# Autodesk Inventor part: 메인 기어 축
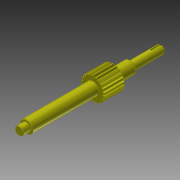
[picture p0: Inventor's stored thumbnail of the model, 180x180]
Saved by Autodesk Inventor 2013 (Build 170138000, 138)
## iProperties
Created: 2018-12
Part Number: 메인 기어 축
Material: 강철, 연강
Document SubType Name: Modeling
Designer: mduedu
Categories: <?xml version="1.0" encoding="UTF-16"?> <MemberInstance><Categories><FamilyTemplate><FamilyTemplateParameter ValueType="xs:double" Id="1" ObjectReferenceKey="da
Density: 7.86 g/cm^3
Mass: 139.66 g
Surface Area: 68.5733 cm^2
Volume: 17.7684 cm^3
CustomPartVersion: 1
Author: mduedu
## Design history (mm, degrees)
sketch "Sketch1"
  geometry: C1 r 11.3 at (0, 0)
  constraints: 1 centre point
  dimensions: "d0" = 22.6 diameter of C1 (= da_da)
extrude "Extrusion1" new body sketch "Sketch1" distance "d1" = 20 (= da_b); taper "d2" = 0 deg
workplane "Work Plane2"
sketch "Sketch2"
  geometry: C1 r 11.3 at (0, 0) reference; C2 r 10.5 at (0, 0)
  constraints: 1 centre point, 1 coincident
  dimensions: "d3" = 21 diameter of C2 (= da_dw)
feature "피치 지름" sketch "Sketch2" dims "d4" = 10, "d5" = 0
workplane "Work Plane8"
workplane "Work Plane9"
chamfer "모따기1" distance "d49" = 0.5; stored, may be unused: second distance "d50" = 2, angle "d51" = 45 deg
sketch "스케치3"
  geometry: C1 r 6 at (0, 0); 1 further point
  constraints: 1 centre point, 1 coincident
  dimensions: "d52" = 12 diameter of C1
extrude "돌출2" join sketch "스케치3" distance "d53" = 64; taper "d54" = 0 deg
sketch "스케치4"
  geometry: C1 r 4 at (0, 0); 1 further point
  constraints: 1 centre point, 1 coincident
  dimensions: "d55" = 8 diameter of C1
extrude "돌출3" join sketch "스케치4" distance "d56" = 7; taper "d57" = 0 deg
sketch "스케치5"
  geometry: C1 r 6 at (0, 0) reference; C2 r 6 at (0, 0) reference; 1 further point
extrude "돌출4" join sketch "스케치5" distance "d58" = 16; taper "d59" = 0 deg
sketch "스케치6"
  geometry: C1 r 4 at (0, 0); 1 further point
  constraints: 1 centre point, 1 coincident
  dimensions: "d60" = 8 diameter of C1
extrude "돌출5" join sketch "스케치6" distance "d61" = 30; taper "d62" = 0 deg
chamfer "모따기2" distance "d63" = 0.5; stored, may be unused: second distance "d64" = 2, angle "d65" = 45 deg
fillet "모깎기1" dims "d66" = 0.5
feature "스퍼 기어" dims "da_b" = 20, "da_d" = 21, "da_aw" = 31, "da_da" = 22.6, "da_df" = 19.086, "da_dw" = 21, angle "da_beta" = 0 deg, "da_lefttooth" = 0, "da_righttooth" = 0
sketch "스케치7" dims "d67" = 18
  geometry: C1 r 0.25 at (0, -9); 2 further points
  constraints: 2 vertical alignment, 1 centre point, 1 coincident, 2 other
  dimensions: "d68" = 0.5 diameter of C1
extrude "돌출6" join sketch "스케치7" distance "d69" = 0.3; taper "d70" = 0 deg
sketch "스케치8"
  geometry: L1 (4, -16)-(4, -45.5) reference; L2 (3.5, -46)-(-3.5, -46) reference; L3 (4, -46)-(2.8, -46); L4 (2.8, -46)-(2.8, -36); L5 (2.8, -36)-(4, -36); L6 (4, -36)-(4, -46); 1 further point
  constraints: 8 end point, 2 parallel, 2 point on line, 1 horizontal, 1 perpendicular
  dimensions: "d72" = 1.2 distance between parallel lines of L4 L6; "d74" = 10 distance between parallel lines of L5 L3
extrude "돌출7" cut sketch "스케치8" stored distance "d75" = 2; taper "d76" = 0 deg
fillet "모깎기2"
body "Solid1"
body "Srf1"
node "투영된 루프1"
other parameters: "d16" = 31 (= da_aw), "d17" = 0, "d34" = 1.496 (computed from da_z), "d39" = 0, "d41" = 0, "d43" = 31 (= da_aw), "d46" = 31 (= da_aw), "d47" = 0, "d48" = 0
